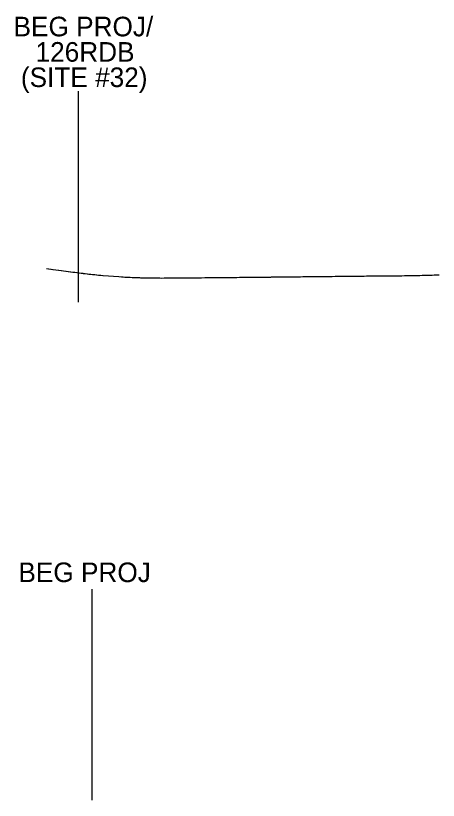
# Model space of a CAD drawing. Extents: x 1876258 to 1926563, y 729739 to 834437.
# Drawn here: x 1878205 to 1880363, y 818055 to 822059 of the extents above; entities that cross this region are included whole.
import ezdxf

# ---------------------------------------------------------------- set-up
doc = ezdxf.new("R2010")
doc.units = 0
doc.layers.add('RD_HC_Data_Tic', color=7, linetype='Continuous')

msp = doc.modelspace()

# ---------------------------------------------------------------- linework, layer by layer
at = {"layer": 'RD_HC_Data_Tic'}
for p, q in [((1878525, 820596.8), (1878525, 821674.8)), ((1878525, 820596.8), (1878525, 821674.8)), ((1878525, 820596.8), (1878525, 821674.8)), ((1878593, 819133.3), (1878593, 818055.3)), ((1878593, 819133.3), (1878593, 818055.3)), ((1878593, 819133.3), (1878593, 818055.3))]:
    msp.add_line(p, q, dxfattribs=at)
msp.add_lwpolyline([(1878363.2, 820769.1), (1878373.3, 820767.8), (1878374.4, 820767.6), (1878384.2, 820766.1), (1878385.5, 820766), (1878395.3, 820764.8), (1878396.3, 820764.6), (1878409.2, 820762.8), (1878409.8, 820762.7), (1878410.8, 820762.6), (1878424.1, 820760.8), (1878424.9, 820760.7), (1878437.3, 820759), (1878438.4, 820758.9), (1878449, 820757.5), (1878449.9, 820757.4), (1878461.7, 820755.8), (1878463.4, 820755.5), (1878472.7, 820754.4), (1878474.8, 820754.1), (1878484.2, 820752.9), (1878485.8, 820752.7), (1878487.3, 820752.5), (1878497, 820751.2), (1878498.5, 820751.1), (1878507.7, 820749.9), (1878517.8, 820748.5), (1878519.1, 820748.4), (1878528.3, 820747.1), (1878529.5, 820747), (1878539.7, 820745.7), (1878540.5, 820745.6), (1878549, 820744.6), (1878550.1, 820744.4), (1878558.8, 820743.4), (1878560, 820743.2), (1878570.4, 820742), (1878571.4, 820741.9), (1878578.5, 820740.9), (1878579.9, 820740.8), (1878587.1, 820740.3), (1878588.2, 820740.1), (1878597.7, 820739.1), (1878599.1, 820739), (1878607, 820738.2), (1878608.4, 820738), (1878617.7, 820737.1), (1878619.2, 820736.9), (1878628.5, 820736), (1878630.1, 820735.8), (1878637.9, 820735.1), (1878639.7, 820735), (1878649.4, 820734.1), (1878650.9, 820734), (1878652.1, 820733.9), (1878652.4, 820733.9), (1878731.3, 820727.6), (1878745.7, 820726.6), (1878753.5, 820726.2), (1878762.4, 820725.6), (1878764, 820725.5), (1878769.1, 820725.3), (1878775.8, 820725.1), (1878777.9, 820725), (1878787, 820724.4), (1878790.4, 820724.2), (1878799.4, 820723.9), (1878802.1, 820723.8), (1878810.4, 820723.5), (1878813.5, 820723.3), (1878821.9, 820723.1), (1878825.1, 820723), (1878833.5, 820722.8), (1878836.4, 820722.7), (1878842.5, 820722.4), (1878845.5, 820722.4), (1878852.6, 820722.2), (1878855.7, 820722.1), (1878862.6, 820722), (1878865.6, 820721.9), (1878874.5, 820721.7), (1878876.6, 820721.7), (1878885.9, 820721.5), (1878887.2, 820721.4), (1878897.8, 820721.3), (1878898.9, 820721.2), (1878909.4, 820721.1), (1878910.4, 820721.1), (1878923.8, 820720.9), (1878925.5, 820720.9), (1878932.8, 820720.9), (1878933.6, 820720.9), (1878940.6, 820720.8), (1878941.2, 820720.8), (1878950.7, 820720.7), (1878951.4, 820720.7), (1878962.4, 820720.8), (1878963.2, 820720.8), (1878973.9, 820720.9), (1878974.1, 820720.9), (1878974.6, 820720.9), (1878985.9, 820720.9), (1878986.7, 820721), (1878987.6, 820721), (1879005.6, 820721), (1879006.4, 820721), (1879017.8, 820721.2), (1879018.3, 820721.2), (1879027.7, 820721.3), (1879028.4, 820721.3), (1879039.4, 820721.4), (1879040.4, 820721.4), (1879058.7, 820721.4), (1879060.1, 820721.4), (1879060.4, 820721.4), (1879074.5, 820721.7), (1879075.8, 820721.7), (1879076.7, 820721.7), (1879087.3, 820721.9), (1879088.8, 820721.9), (1879099, 820722), (1879100.2, 820722), (1879109.7, 820722.1), (1879111.2, 820722.1), (1879120.7, 820722.2), (1879122.5, 820722.2), (1879123.7, 820722.2), (1879136.7, 820722.1), (1879137.4, 820722.1), (1879150.2, 820722.3), (1879152.3, 820722.3), (1879154.3, 820722.3), (1879171.2, 820722.5), (1879174.2, 820722.6), (1879187.3, 820722.6), (1879190.7, 820722.7), (1879203.5, 820722.8), (1879206.9, 820722.9), (1879219.8, 820723), (1879222.8, 820723), (1879235.8, 820723.2), (1879239, 820723.2), (1879251.8, 820723.3), (1879254.8, 820723.3), (1879267.8, 820723.5), (1879270.7, 820723.5), (1879283.9, 820723.6), (1879287, 820723.6), (1879300.1, 820723.7), (1879303.3, 820723.7), (1879318.9, 820723.9), (1879320.4, 820723.9), (1879331.5, 820724), (1879334.9, 820724.1), (1879348, 820724.3), (1879351.6, 820724.3), (1879364.2, 820724.4), (1879367.5, 820724.5), (1879381.2, 820724.7), (1879384.2, 820724.8), (1879394.6, 820724.8), (1879397.6, 820724.8), (1879410, 820725), (1879413, 820725), (1879424.2, 820725.1), (1879427.6, 820725.2), (1879437.6, 820725.3), (1879441.2, 820725.3), (1879450.9, 820725.4), (1879458.5, 820725.3), (1879462.3, 820725.3), (1879472.9, 820725.6), (1879476.1, 820725.6), (1879487.5, 820725.6), (1879489.9, 820725.5), (1879494.6, 820725.6), (1879507, 820725.8), (1879511.3, 820725.9), (1879523.7, 820726.2), (1879528.2, 820726.2), (1879540.6, 820726.3), (1879544.5, 820726.3), (1879556.7, 820726.4), (1879560.8, 820726.5), (1879573.2, 820726.6), (1879583, 820726.7), (1879586.5, 820726.7), (1879599.6, 820726.8), (1879602.7, 820726.8), (1879615.7, 820727), (1879618.5, 820727), (1879632.5, 820727.2), (1879635.2, 820727.2), (1879649.6, 820727.3), (1879652.5, 820727.4), (1879659.2, 820727.5), (1879671.6, 820727.6), (1879675, 820727.7), (1879687.6, 820727.8), (1879691.6, 820727.9), (1879704.7, 820728.1), (1879708, 820728.1), (1879721.6, 820728.2), (1879724.7, 820728.2), (1879737.5, 820728.4), (1879741.1, 820728.4), (1879753.7, 820728.5), (1879758, 820728.5), (1879769, 820728.6), (1879772, 820728.7), (1879785.1, 820728.9), (1879787.6, 820728.9), (1879802.2, 820729), (1879804.7, 820729), (1879818.1, 820729.2), (1879821, 820729.2), (1879835.7, 820729.3), (1879838.3, 820729.3), (1879853.8, 820729.5), (1879854.9, 820729.5), (1879856.3, 820729.5), (1879871.8, 820729.7), (1879873.5, 820729.7), (1879888.4, 820729.8), (1879890.3, 820729.8), (1879899.4, 820729.8), (1879916.1, 820730), (1879918.7, 820730.1), (1879921.2, 820730.1), (1879935.4, 820730.2), (1879939.5, 820730.2), (1879951.3, 820730.3), (1879962.7, 820730.5), (1879967.4, 820730.5), (1879979.2, 820730.7), (1879983.9, 820730.7), (1879995.8, 820731), (1880000.8, 820731.1), (1880010.6, 820731.2), (1880015.2, 820731.3), (1880026.3, 820731.3), (1880029.4, 820731.3), (1880038.1, 820731.4), (1880046.6, 820731.4), (1880059.4, 820731.3), (1880060.5, 820731.4), (1880073.8, 820731.5), (1880077.2, 820731.5), (1880090.5, 820731.7), (1880093.9, 820731.7), (1880106.1, 820731.8), (1880110.3, 820731.9), (1880122, 820731.9), (1880125.8, 820732), (1880130, 820732), (1880141.7, 820732.1), (1880144, 820732.2), (1880157.2, 820732.3), (1880160.6, 820732.3), (1880173.3, 820732.5), (1880176.2, 820732.5), (1880190.7, 820732.7), (1880193.3, 820732.7), (1880204.9, 820732.9), (1880207, 820732.9), (1880218.6, 820733.2), (1880220.5, 820733.2), (1880237.6, 820733.6), (1880237.9, 820733.6), (1880238.2, 820733.6), (1880250.3, 820733.8), (1880252.1, 820733.9), (1880252.1, 820733.9), (1880267.1, 820734.2), (1880267.2, 820734.2), (1880267.4, 820734.2), (1880269.4, 820734.2), (1880279.8, 820734.4), (1880280.5, 820734.4), (1880292.4, 820734.8), (1880293.6, 820734.9), (1880304.6, 820735.2), (1880305.6, 820735.2), (1880317.6, 820735.5), (1880318.8, 820735.5), (1880329.9, 820735.9), (1880331.1, 820736), (1880341.9, 820736.4), (1880343.3, 820736.4), (1880353.3, 820736.7), (1880355, 820736.8), (1880366.6, 820737.2)], dxfattribs=at)
msp.add_lwpolyline([(1878363.2, 820769.1), (1878373.3, 820767.8), (1878374.4, 820767.6), (1878384.2, 820766.1), (1878385.5, 820766), (1878395.3, 820764.8), (1878396.3, 820764.6), (1878409.2, 820762.8), (1878409.8, 820762.7), (1878410.8, 820762.6), (1878424.1, 820760.8), (1878424.9, 820760.7), (1878437.3, 820759), (1878438.4, 820758.9), (1878449, 820757.5), (1878449.9, 820757.4), (1878461.7, 820755.8), (1878463.4, 820755.5), (1878472.7, 820754.4), (1878474.8, 820754.1), (1878484.2, 820752.9), (1878485.8, 820752.7), (1878487.3, 820752.5), (1878497, 820751.2), (1878498.5, 820751.1), (1878507.7, 820749.9), (1878517.8, 820748.5), (1878519.1, 820748.4), (1878528.3, 820747.1), (1878529.5, 820747), (1878539.7, 820745.7), (1878540.5, 820745.6), (1878549, 820744.6), (1878550.1, 820744.4), (1878558.8, 820743.4), (1878560, 820743.2), (1878570.4, 820742), (1878571.4, 820741.9), (1878578.5, 820740.9), (1878579.9, 820740.8), (1878587.1, 820740.3), (1878588.2, 820740.1), (1878597.7, 820739.1), (1878599.1, 820739), (1878607, 820738.2), (1878608.4, 820738), (1878617.7, 820737.1), (1878619.2, 820736.9), (1878628.5, 820736), (1878630.1, 820735.8), (1878637.9, 820735.1), (1878639.7, 820735), (1878649.4, 820734.1), (1878650.9, 820734), (1878652.1, 820733.9), (1878652.4, 820733.9), (1878731.3, 820727.6), (1878745.7, 820726.6), (1878753.5, 820726.2), (1878762.4, 820725.6), (1878764, 820725.5), (1878769.1, 820725.3), (1878775.8, 820725.1), (1878777.9, 820725), (1878787, 820724.4), (1878790.4, 820724.2), (1878799.4, 820723.9), (1878802.1, 820723.8), (1878810.4, 820723.5), (1878813.5, 820723.3), (1878821.9, 820723.1), (1878825.1, 820723), (1878833.5, 820722.8), (1878836.4, 820722.7), (1878842.5, 820722.4), (1878845.5, 820722.4), (1878852.6, 820722.2), (1878855.7, 820722.1), (1878862.6, 820722), (1878865.6, 820721.9), (1878874.5, 820721.7), (1878876.6, 820721.7), (1878885.9, 820721.5), (1878887.2, 820721.4), (1878897.8, 820721.3), (1878898.9, 820721.2), (1878909.4, 820721.1), (1878910.4, 820721.1), (1878923.8, 820720.9), (1878925.5, 820720.9), (1878932.8, 820720.9), (1878933.6, 820720.9), (1878940.6, 820720.8), (1878941.2, 820720.8), (1878950.7, 820720.7), (1878951.4, 820720.7), (1878962.4, 820720.8), (1878963.2, 820720.8), (1878973.9, 820720.9), (1878974.1, 820720.9), (1878974.6, 820720.9), (1878985.9, 820720.9), (1878986.7, 820721), (1878987.6, 820721), (1879005.6, 820721), (1879006.4, 820721), (1879017.8, 820721.2), (1879018.3, 820721.2), (1879027.7, 820721.3), (1879028.4, 820721.3), (1879039.4, 820721.4), (1879040.4, 820721.4), (1879058.7, 820721.4), (1879060.1, 820721.4), (1879060.4, 820721.4), (1879074.5, 820721.7), (1879075.8, 820721.7), (1879076.7, 820721.7), (1879087.3, 820721.9), (1879088.8, 820721.9), (1879099, 820722), (1879100.2, 820722), (1879109.7, 820722.1), (1879111.2, 820722.1), (1879120.7, 820722.2), (1879122.5, 820722.2), (1879123.7, 820722.2), (1879136.7, 820722.1), (1879137.4, 820722.1), (1879150.2, 820722.3), (1879152.3, 820722.3), (1879154.3, 820722.3), (1879171.2, 820722.5), (1879174.2, 820722.6), (1879187.3, 820722.6), (1879190.7, 820722.7), (1879203.5, 820722.8), (1879206.9, 820722.9), (1879219.8, 820723), (1879222.8, 820723), (1879235.8, 820723.2), (1879239, 820723.2), (1879251.8, 820723.3), (1879254.8, 820723.3), (1879267.8, 820723.5), (1879270.7, 820723.5), (1879283.9, 820723.6), (1879287, 820723.6), (1879300.1, 820723.7), (1879303.3, 820723.7), (1879318.9, 820723.9), (1879320.4, 820723.9), (1879331.5, 820724), (1879334.9, 820724.1), (1879348, 820724.3), (1879351.6, 820724.3), (1879364.2, 820724.4), (1879367.5, 820724.5), (1879381.2, 820724.7), (1879384.2, 820724.8), (1879394.6, 820724.8), (1879397.6, 820724.8), (1879410, 820725), (1879413, 820725), (1879424.2, 820725.1), (1879427.6, 820725.2), (1879437.6, 820725.3), (1879441.2, 820725.3), (1879450.9, 820725.4), (1879458.5, 820725.3), (1879462.3, 820725.3), (1879472.9, 820725.6), (1879476.1, 820725.6), (1879487.5, 820725.6), (1879489.9, 820725.5), (1879494.6, 820725.6), (1879507, 820725.8), (1879511.3, 820725.9), (1879523.7, 820726.2), (1879528.2, 820726.2), (1879540.6, 820726.3), (1879544.5, 820726.3), (1879556.7, 820726.4), (1879560.8, 820726.5), (1879573.2, 820726.6), (1879583, 820726.7), (1879586.5, 820726.7), (1879599.6, 820726.8), (1879602.7, 820726.8), (1879615.7, 820727), (1879618.5, 820727), (1879632.5, 820727.2), (1879635.2, 820727.2), (1879649.6, 820727.3), (1879652.5, 820727.4), (1879659.2, 820727.5), (1879671.6, 820727.6), (1879675, 820727.7), (1879687.6, 820727.8), (1879691.6, 820727.9), (1879704.7, 820728.1), (1879708, 820728.1), (1879721.6, 820728.2), (1879724.7, 820728.2), (1879737.5, 820728.4), (1879741.1, 820728.4), (1879753.7, 820728.5), (1879758, 820728.5), (1879769, 820728.6), (1879772, 820728.7), (1879785.1, 820728.9), (1879787.6, 820728.9), (1879802.2, 820729), (1879804.7, 820729), (1879818.1, 820729.2), (1879821, 820729.2), (1879835.7, 820729.3), (1879838.3, 820729.3), (1879853.8, 820729.5), (1879854.9, 820729.5), (1879856.3, 820729.5), (1879871.8, 820729.7), (1879873.5, 820729.7), (1879888.4, 820729.8), (1879890.3, 820729.8), (1879899.4, 820729.8), (1879916.1, 820730), (1879918.7, 820730.1), (1879921.2, 820730.1), (1879935.4, 820730.2), (1879939.5, 820730.2), (1879951.3, 820730.3), (1879962.7, 820730.5), (1879967.4, 820730.5), (1879979.2, 820730.7), (1879983.9, 820730.7), (1879995.8, 820731), (1880000.8, 820731.1), (1880010.6, 820731.2), (1880015.2, 820731.3), (1880026.3, 820731.3), (1880029.4, 820731.3), (1880038.1, 820731.4), (1880046.6, 820731.4), (1880059.4, 820731.3), (1880060.5, 820731.4), (1880073.8, 820731.5), (1880077.2, 820731.5), (1880090.5, 820731.7), (1880093.9, 820731.7), (1880106.1, 820731.8), (1880110.3, 820731.9), (1880122, 820731.9), (1880125.8, 820732), (1880130, 820732), (1880141.7, 820732.1), (1880144, 820732.2), (1880157.2, 820732.3), (1880160.6, 820732.3), (1880173.3, 820732.5), (1880176.2, 820732.5), (1880190.7, 820732.7), (1880193.3, 820732.7), (1880204.9, 820732.9), (1880207, 820732.9), (1880218.6, 820733.2), (1880220.5, 820733.2), (1880237.6, 820733.6), (1880237.9, 820733.6), (1880238.2, 820733.6), (1880250.3, 820733.8), (1880252.1, 820733.9), (1880252.1, 820733.9), (1880267.1, 820734.2), (1880267.2, 820734.2), (1880267.4, 820734.2), (1880269.4, 820734.2), (1880279.8, 820734.4), (1880280.5, 820734.4), (1880292.4, 820734.8), (1880293.6, 820734.9), (1880304.6, 820735.2), (1880305.6, 820735.2), (1880317.6, 820735.5), (1880318.8, 820735.5), (1880329.9, 820735.9), (1880331.1, 820736), (1880341.9, 820736.4), (1880343.3, 820736.4), (1880353.3, 820736.7), (1880355, 820736.8), (1880366.6, 820737.2)], dxfattribs=at)
msp.add_lwpolyline([(1878363.2, 820769.1), (1878373.3, 820767.8), (1878374.4, 820767.6), (1878384.2, 820766.1), (1878385.5, 820766), (1878395.3, 820764.8), (1878396.3, 820764.6), (1878409.2, 820762.8), (1878409.8, 820762.7), (1878410.8, 820762.6), (1878424.1, 820760.8), (1878424.9, 820760.7), (1878437.3, 820759), (1878438.4, 820758.9), (1878449, 820757.5), (1878449.9, 820757.4), (1878461.7, 820755.8), (1878463.4, 820755.5), (1878472.7, 820754.4), (1878474.8, 820754.1), (1878484.2, 820752.9), (1878485.8, 820752.7), (1878487.3, 820752.5), (1878497, 820751.2), (1878498.5, 820751.1), (1878507.7, 820749.9), (1878517.8, 820748.5), (1878519.1, 820748.4), (1878528.3, 820747.1), (1878529.5, 820747), (1878539.7, 820745.7), (1878540.5, 820745.6), (1878549, 820744.6), (1878550.1, 820744.4), (1878558.8, 820743.4), (1878560, 820743.2), (1878570.4, 820742), (1878571.4, 820741.9), (1878578.5, 820740.9), (1878579.9, 820740.8), (1878587.1, 820740.3), (1878588.2, 820740.1), (1878597.7, 820739.1), (1878599.1, 820739), (1878607, 820738.2), (1878608.4, 820738), (1878617.7, 820737.1), (1878619.2, 820736.9), (1878628.5, 820736), (1878630.1, 820735.8), (1878637.9, 820735.1), (1878639.7, 820735), (1878649.4, 820734.1), (1878650.9, 820734), (1878652.1, 820733.9), (1878652.4, 820733.9), (1878731.3, 820727.6), (1878745.7, 820726.6), (1878753.5, 820726.2), (1878762.4, 820725.6), (1878764, 820725.5), (1878769.1, 820725.3), (1878775.8, 820725.1), (1878777.9, 820725), (1878787, 820724.4), (1878790.4, 820724.2), (1878799.4, 820723.9), (1878802.1, 820723.8), (1878810.4, 820723.5), (1878813.5, 820723.3), (1878821.9, 820723.1), (1878825.1, 820723), (1878833.5, 820722.8), (1878836.4, 820722.7), (1878842.5, 820722.4), (1878845.5, 820722.4), (1878852.6, 820722.2), (1878855.7, 820722.1), (1878862.6, 820722), (1878865.6, 820721.9), (1878874.5, 820721.7), (1878876.6, 820721.7), (1878885.9, 820721.5), (1878887.2, 820721.4), (1878897.8, 820721.3), (1878898.9, 820721.2), (1878909.4, 820721.1), (1878910.4, 820721.1), (1878923.8, 820720.9), (1878925.5, 820720.9), (1878932.8, 820720.9), (1878933.6, 820720.9), (1878940.6, 820720.8), (1878941.2, 820720.8), (1878950.7, 820720.7), (1878951.4, 820720.7), (1878962.4, 820720.8), (1878963.2, 820720.8), (1878973.9, 820720.9), (1878974.1, 820720.9), (1878974.6, 820720.9), (1878985.9, 820720.9), (1878986.7, 820721), (1878987.6, 820721), (1879005.6, 820721), (1879006.4, 820721), (1879017.8, 820721.2), (1879018.3, 820721.2), (1879027.7, 820721.3), (1879028.4, 820721.3), (1879039.4, 820721.4), (1879040.4, 820721.4), (1879058.7, 820721.4), (1879060.1, 820721.4), (1879060.4, 820721.4), (1879074.5, 820721.7), (1879075.8, 820721.7), (1879076.7, 820721.7), (1879087.3, 820721.9), (1879088.8, 820721.9), (1879099, 820722), (1879100.2, 820722), (1879109.7, 820722.1), (1879111.2, 820722.1), (1879120.7, 820722.2), (1879122.5, 820722.2), (1879123.7, 820722.2), (1879136.7, 820722.1), (1879137.4, 820722.1), (1879150.2, 820722.3), (1879152.3, 820722.3), (1879154.3, 820722.3), (1879171.2, 820722.5), (1879174.2, 820722.6), (1879187.3, 820722.6), (1879190.7, 820722.7), (1879203.5, 820722.8), (1879206.9, 820722.9), (1879219.8, 820723), (1879222.8, 820723), (1879235.8, 820723.2), (1879239, 820723.2), (1879251.8, 820723.3), (1879254.8, 820723.3), (1879267.8, 820723.5), (1879270.7, 820723.5), (1879283.9, 820723.6), (1879287, 820723.6), (1879300.1, 820723.7), (1879303.3, 820723.7), (1879318.9, 820723.9), (1879320.4, 820723.9), (1879331.5, 820724), (1879334.9, 820724.1), (1879348, 820724.3), (1879351.6, 820724.3), (1879364.2, 820724.4), (1879367.5, 820724.5), (1879381.2, 820724.7), (1879384.2, 820724.8), (1879394.6, 820724.8), (1879397.6, 820724.8), (1879410, 820725), (1879413, 820725), (1879424.2, 820725.1), (1879427.6, 820725.2), (1879437.6, 820725.3), (1879441.2, 820725.3), (1879450.9, 820725.4), (1879458.5, 820725.3), (1879462.3, 820725.3), (1879472.9, 820725.6), (1879476.1, 820725.6), (1879487.5, 820725.6), (1879489.9, 820725.5), (1879494.6, 820725.6), (1879507, 820725.8), (1879511.3, 820725.9), (1879523.7, 820726.2), (1879528.2, 820726.2), (1879540.6, 820726.3), (1879544.5, 820726.3), (1879556.7, 820726.4), (1879560.8, 820726.5), (1879573.2, 820726.6), (1879583, 820726.7), (1879586.5, 820726.7), (1879599.6, 820726.8), (1879602.7, 820726.8), (1879615.7, 820727), (1879618.5, 820727), (1879632.5, 820727.2), (1879635.2, 820727.2), (1879649.6, 820727.3), (1879652.5, 820727.4), (1879659.2, 820727.5), (1879671.6, 820727.6), (1879675, 820727.7), (1879687.6, 820727.8), (1879691.6, 820727.9), (1879704.7, 820728.1), (1879708, 820728.1), (1879721.6, 820728.2), (1879724.7, 820728.2), (1879737.5, 820728.4), (1879741.1, 820728.4), (1879753.7, 820728.5), (1879758, 820728.5), (1879769, 820728.6), (1879772, 820728.7), (1879785.1, 820728.9), (1879787.6, 820728.9), (1879802.2, 820729), (1879804.7, 820729), (1879818.1, 820729.2), (1879821, 820729.2), (1879835.7, 820729.3), (1879838.3, 820729.3), (1879853.8, 820729.5), (1879854.9, 820729.5), (1879856.3, 820729.5), (1879871.8, 820729.7), (1879873.5, 820729.7), (1879888.4, 820729.8), (1879890.3, 820729.8), (1879899.4, 820729.8), (1879916.1, 820730), (1879918.7, 820730.1), (1879921.2, 820730.1), (1879935.4, 820730.2), (1879939.5, 820730.2), (1879951.3, 820730.3), (1879962.7, 820730.5), (1879967.4, 820730.5), (1879979.2, 820730.7), (1879983.9, 820730.7), (1879995.8, 820731), (1880000.8, 820731.1), (1880010.6, 820731.2), (1880015.2, 820731.3), (1880026.3, 820731.3), (1880029.4, 820731.3), (1880038.1, 820731.4), (1880046.6, 820731.4), (1880059.4, 820731.3), (1880060.5, 820731.4), (1880073.8, 820731.5), (1880077.2, 820731.5), (1880090.5, 820731.7), (1880093.9, 820731.7), (1880106.1, 820731.8), (1880110.3, 820731.9), (1880122, 820731.9), (1880125.8, 820732), (1880130, 820732), (1880141.7, 820732.1), (1880144, 820732.2), (1880157.2, 820732.3), (1880160.6, 820732.3), (1880173.3, 820732.5), (1880176.2, 820732.5), (1880190.7, 820732.7), (1880193.3, 820732.7), (1880204.9, 820732.9), (1880207, 820732.9), (1880218.6, 820733.2), (1880220.5, 820733.2), (1880237.6, 820733.6), (1880237.9, 820733.6), (1880238.2, 820733.6), (1880250.3, 820733.8), (1880252.1, 820733.9), (1880252.1, 820733.9), (1880267.1, 820734.2), (1880267.2, 820734.2), (1880267.4, 820734.2), (1880269.4, 820734.2), (1880279.8, 820734.4), (1880280.5, 820734.4), (1880292.4, 820734.8), (1880293.6, 820734.9), (1880304.6, 820735.2), (1880305.6, 820735.2), (1880317.6, 820735.5), (1880318.8, 820735.5), (1880329.9, 820735.9), (1880331.1, 820736), (1880341.9, 820736.4), (1880343.3, 820736.4), (1880353.3, 820736.7), (1880355, 820736.8), (1880366.6, 820737.2)], dxfattribs=at)

# ---------------------------------------------------------------- texts
for s, p in [('BEG PROJ/', (1878194.1, 821954)), ('BEG PROJ/', (1878194.1, 821954)), ('BEG PROJ/', (1878194.1, 821954)), ('126RDB ', (1878306.5, 821824.6)), ('126RDB ', (1878306.5, 821824.6)), ('126RDB ', (1878306.5, 821824.6)), ('(SITE #32)', (1878231.6, 821695.2)), ('(SITE #32)', (1878231.6, 821695.2)), ('(SITE #32)', (1878231.6, 821695.2)), ('BEG PROJ', (1878218.9, 819168.8)), ('BEG PROJ', (1878218.9, 819168.8)), ('BEG PROJ', (1878218.9, 819168.8))]:
    msp.add_text(s, height=100, dxfattribs=at).set_placement(p)

doc.saveas('drawing.dxf')
